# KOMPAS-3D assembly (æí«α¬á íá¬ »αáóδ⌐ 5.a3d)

Referenced files in D:\АСКОН работа\Конкурс HOME\06_Сюваев_Сборная модель танка Т90\ДЕТАЛИ\КОРПУС\МЕТАЛЛ\КОРПУС ШТАМПОВКА\БАКИ\: бак правый 5.m3d
Referenced files in D:\АСКОН работа\Конкурс HOME\06_Сюваев_Сборная модель танка Т90\ДЕТАЛИ\ОБЩИЕ ДЕТАЛИ\: ручки баков.m3d
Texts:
  Сборка бак правый 5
